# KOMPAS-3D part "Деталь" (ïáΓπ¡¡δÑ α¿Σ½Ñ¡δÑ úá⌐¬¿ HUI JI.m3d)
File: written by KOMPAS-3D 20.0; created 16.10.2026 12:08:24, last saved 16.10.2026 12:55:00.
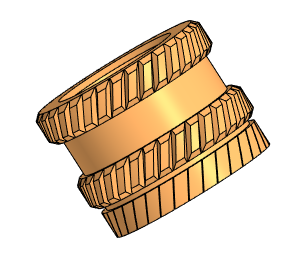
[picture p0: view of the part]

Document properties: Полное имя файла: D:\RicWork\Project-EPS32\box_compas\прочее\Латунные рифленые гайки HUI JI.m3d

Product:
- Part/product: Деталь
    Масса: 0.000148431
  - Body: Тело 1
      Масса: 0.000275726

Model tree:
1. Эскиз:1
2. Элемент выдавливания:1
     Расстояние 1 = 0.75
3. Эскиз:2  (with: Элемент выдавливания:1)
4. Элемент выдавливания:2
     Расстояние 1 = 0.75
5. Эскиз:3  (with: Элемент выдавливания:2)
6. Элемент выдавливания:3
     Расстояние 1 = 0.125
7. Эскиз:4  (with: Элемент выдавливания:3)
8. Элемент выдавливания:4
     Расстояние 1 = 0.75
9. Эскиз:5  (with: Элемент выдавливания:4)
10. Элемент выдавливания:5
     Расстояние 1 = 0.125
11. Эскиз:6  (with: Элемент выдавливания:5)
12. Элемент выдавливания:6
     Расстояние 1 = 0.6
13. Фаска:1  (with: Элемент выдавливания:4, Элемент выдавливания:1)
     Угол = 45; Длина 1 = 0.125; Длина 2 = 0.125
14. Эскиз:10  (with: Элемент выдавливания:1)
15. Спираль:2  (with: Элемент выдавливания:6)
     Число витков = 0.15; Шаг = 20.6667; Высота = 3.1; Диаметр 1 = 4; Диаметр 2 = 10
16. Перпендикулярная плоскость:3
17. Эскиз:11
18. Элемент по траектории:3
19. Массив по концентрической сетке:2  (with: Элемент по траектории:3, Спираль:2, Эскиз:11, Эскиз:10, Элемент выдавливания:1)  (33 pattern instances)
     Шаг 2 = 360
20. Элемент выдавливания:8
     Расстояние 2 = 3.1
21. Фаска:2  (with: Элемент выдавливания:8)
     Угол = 45; Длина 1 = 0.125; Длина 2 = 0.125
